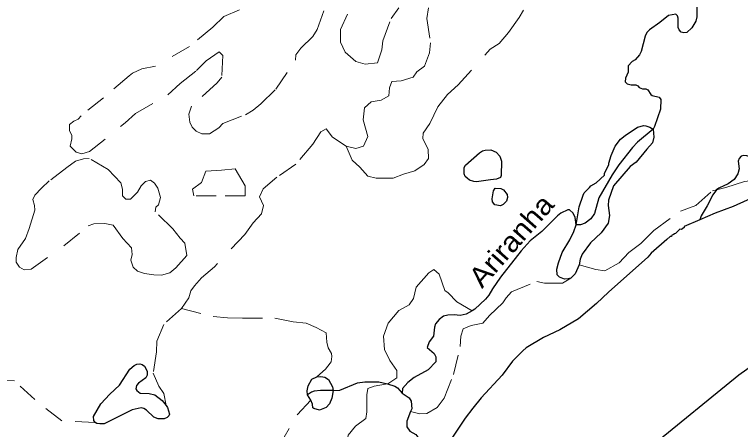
# Model space of a CAD drawing. Extents: x 344.9 to 371, y 7566.4 to 7594.3.
# Drawn here: x 363.484 to 367.111, y 7574.277 to 7576.351 of the extents above; entities that cross this region are included whole.
import ezdxf
from ezdxf.enums import TextEntityAlignment as Align

# ---------------------------------------------------------------- set-up
doc = ezdxf.new("R2010")
doc.units = 0
doc.header["$LTSCALE"] = 0.04
doc.linetypes.add('LONG_DASHED', pattern=[7.5, 6, -1.5])
doc.linetypes.add('SHORT_DASHED', pattern=[2.7, 1.5, -1.2])
for name, color, linetype, lineweight in [('17', 7, 'SHORT_DASHED', 13), ('2', 7, 'Continuous', 25), ('21', 7, 'SHORT_DASHED', 13), ('3', 7, 'LONG_DASHED', 25), ('55', 7, 'Continuous', 25), ('7', 7, 'Continuous', 25)]:
    doc.layers.add(name, color=color, linetype=linetype, lineweight=lineweight)
doc.layers.add('61', color=7, linetype='Continuous')

msp = doc.modelspace()

# ---------------------------------------------------------------- linework, layer by layer
at = {"layer": '17'}
for points in [[(365.1404, 7575.6937), (365.171, 7575.6239), (365.2095, 7575.5887), (365.2488, 7575.5427), (365.2915, 7575.5335), (365.3753, 7575.5327), (365.4272, 7575.5528), (365.4833, 7575.57), (365.5302, 7575.601), (365.5519, 7575.6311), (365.5503, 7575.6763), (365.5243, 7575.7324), (365.5251, 7575.7579), (365.5594, 7575.8065), (365.5996, 7575.8893), (365.6473, 7575.9521), (365.7, 7575.999), (365.8607, 7576.1777), (365.9059, 7576.207), (365.9519, 7576.261), (366.0055, 7576.3364), (366.0273, 7576.3724)], [(366.9919, 7575.4754), (367.0379, 7575.4866), (367.1305, 7575.5166), (367.1577, 7575.5202), (367.2629, 7575.5823), (367.3165, 7575.6332), (367.3382, 7575.6581), (367.4017, 7575.6781), (367.4607, 7575.6826), (367.5177, 7575.7012)], [(366.3051, 7575.0995), (366.3883, 7575.0766), (366.4328, 7575.0711), (366.5054, 7575.1101), (366.5534, 7575.1618), (366.6124, 7575.2072), (366.6786, 7575.2725), (366.812, 7575.3691), (366.8883, 7575.3972), (366.9708, 7575.4703), (366.9919, 7575.4754)], [(365.7709, 7574.8707), (365.6932, 7574.9162), (365.6513, 7574.9603), (365.6337, 7574.9713), (365.605, 7575.0529), (365.5785, 7575.0772), (365.5543, 7575.0595), (365.4903, 7574.9889), (365.4771, 7574.9316), (365.455, 7574.9007), (365.4043, 7574.8721), (365.3513, 7574.8081), (365.3271, 7574.7441), (365.3331, 7574.6777), (365.3593, 7574.6227), (365.3945, 7574.5727), (365.3935, 7574.5358), (365.3485, 7574.5063), (365.3482, 7574.5062)], [(365.4628, 7574.3666), (365.5089, 7574.3561), (365.5434, 7574.357), (365.596, 7574.3869), (365.6314, 7574.4332), (365.6768, 7574.5521), (365.7112, 7574.6927), (365.714, 7574.744), (365.7249, 7574.7812), (365.7657, 7574.7966), (365.8237, 7574.8084), (365.8573, 7574.8465), (365.9235, 7574.91), (365.9399, 7574.9354), (365.9671, 7574.9658), (366.0941, 7575.0166), (366.1313, 7575.0079), (366.2211, 7575.0079), (366.2632, 7575.0342)], [(364.3182, 7574.882), (364.4773, 7574.8419), (364.5479, 7574.8352), (364.6229, 7574.833), (364.7839, 7574.833), (364.8765, 7574.8154), (364.9405, 7574.8088), (364.9912, 7574.7867), (365.0419, 7574.7602), (365.0442, 7574.7139), (365.0508, 7574.6853), (365.0682, 7574.6578), (365.0687, 7574.6423), (365.0659, 7574.616), (365.0617, 7574.6091), (365.0377, 7574.5789), (364.994, 7574.5413)], [(365.3482, 7574.5062), (365.2817, 7574.4942), (365.2493, 7574.4831), (365.2438, 7574.4498), (365.2447, 7574.3657), (365.2401, 7574.3324), (365.1883, 7574.294), (365.1514, 7574.2497), (365.144, 7574.2053), (365.1643, 7574.1489), (365.168, 7574.112), (365.1634, 7574.0865), (365.1125, 7574.0431), (365.0737, 7574.0015), (365.0451, 7573.959), (365.0358, 7573.9146), (365.0478, 7573.893), (365.0599, 7573.8514), (365.1141, 7573.8251)], [(364.8063, 7574.1953), (364.8961, 7574.3501), (364.9638, 7574.4239)]]:
    msp.add_lwpolyline(points, dxfattribs=at)
at = {"layer": '2'}
msp.add_line((364.9701, 7574.5286), (364.994, 7574.5413), dxfattribs=at)
for points in [[(366.3574, 7575.4871), (366.3638, 7575.4943), (366.3892, 7575.5101), (366.4313, 7575.549), (366.4313, 7575.5562), (366.4535, 7575.6023), (366.4529, 7575.6086), (366.4647, 7575.6459), (366.4845, 7575.6928), (366.5123, 7575.7277), (366.5345, 7575.7468), (366.5965, 7575.7889), (366.6274, 7575.796), (366.6378, 7575.7952), (366.6584, 7575.7889), (366.6747, 7575.7781)], [(366.6747, 7575.7781), (366.6782, 7575.7389), (366.6711, 7575.7094), (366.6425, 7575.6785), (366.5905, 7575.6134), (366.5599, 7575.5911), (366.4773, 7575.4958), (366.4519, 7575.4228), (366.4503, 7575.3974), (366.4567, 7575.3466), (366.4503, 7575.3085), (366.4154, 7575.2608), (366.3623, 7575.2098), (366.3203, 7575.1537), (366.3092, 7575.1285), (366.3051, 7575.0995)], [(366.3256, 7575.4482), (366.3304, 7575.4593), (366.3574, 7575.4871)], [(367.2143, 7575.4554), (367.0745, 7575.3926), (366.984, 7575.3585), (366.9079, 7575.3257)], [(366.2899, 7575.3005), (366.3058, 7575.3895), (366.3256, 7575.4482)], [(366.9079, 7575.3257), (366.8299, 7575.2926), (366.8291, 7575.287), (366.8156, 7575.2775), (366.8077, 7575.2791), (366.7855, 7575.2568), (366.7783, 7575.256), (366.7775, 7575.2521), (366.768, 7575.2481), (366.7656, 7575.2425), (366.76, 7575.2417), (366.7425, 7575.2266), (366.6655, 7575.1584), (366.6473, 7575.1385)], [(366.2632, 7575.0342), (366.2498, 7575.0296), (366.2314, 7575.0282), (366.2074, 7575.0384), (366.1954, 7575.0504), (366.1938, 7575.0781), (366.201, 7575.1099), (366.22, 7575.1624), (366.2582, 7575.2259), (366.2788, 7575.2672), (366.2899, 7575.3005)], [(366.6473, 7575.1385), (366.451, 7574.9644), (366.3924, 7574.9074), (366.3011, 7574.8304), (366.2082, 7574.7756), (366.1264, 7574.7375), (366.0406, 7574.6851), (366.0231, 7574.6708), (365.9715, 7574.6184), (365.9199, 7574.5485), (365.8158, 7574.435), (365.7738, 7574.3842), (365.7349, 7574.3333), (365.6515, 7574.2087), (365.6308, 7574.1841)], [(366.3051, 7575.0995), (366.2853, 7575.0559), (366.2632, 7575.0342)], [(364.9479, 7574.45), (364.9463, 7574.4699), (364.9511, 7574.4961), (364.9701, 7574.5286)], [(364.994, 7574.5413), (365.0147, 7574.5429), (365.0353, 7574.5382), (365.0536, 7574.5279), (365.0735, 7574.49), (365.0763, 7574.4717)], [(365.0763, 7574.4717), (365.0702, 7574.4334), (365.0583, 7574.4056), (365.0408, 7574.3881), (365.0075, 7574.3746), (364.9789, 7574.3817), (364.9741, 7574.3857), (364.9725, 7574.4032), (364.9638, 7574.4239), (364.9479, 7574.45)]]:
    msp.add_lwpolyline(points, dxfattribs=at)
msp.add_lwpolyline([(365.8706, 7575.4308), (365.877, 7575.4705), (365.8857, 7575.4839), (365.9143, 7575.4824), (365.9263, 7575.4752), (365.9453, 7575.4522), (365.9477, 7575.4371), (365.9421, 7575.4181), (365.9254, 7575.4022), (365.912, 7575.3958), (365.8834, 7575.4005), (365.8722, 7575.4149)], close=True, dxfattribs=at)
at = {"layer": '21'}
msp.add_line((364.0729, 7576.0573), (364.0567, 7576.0455), dxfattribs=at)
for points in [[(364.0567, 7576.0455), (363.9286, 7575.9354), (363.8172, 7575.8457), (363.8018, 7575.8278), (363.7813, 7575.8176), (363.7595, 7575.8009), (363.7583, 7575.7715), (363.7711, 7575.7471), (363.7711, 7575.7292), (363.7621, 7575.6933), (363.7916, 7575.6626), (363.821, 7575.6549), (363.8582, 7575.6664), (364.0375, 7575.8099), (364.0887, 7575.856), (364.2501, 7575.9495), (364.3115, 7576.0058), (364.3935, 7576.0718), (364.4409, 7576.1191), (364.5062, 7576.164), (364.5241, 7576.146), (364.5203, 7576.0385), (364.4959, 7576.009), (364.3679, 7575.8925), (364.355, 7575.854), (364.3602, 7575.8131), (364.3717, 7575.7887), (364.3922, 7575.7682), (364.4204, 7575.7554), (364.4588, 7575.7554), (364.5049, 7575.7849), (364.5254, 7575.8066), (364.6381, 7575.8502), (364.6765, 7575.8726), (364.7149, 7575.9046), (364.7905, 7575.9776), (364.8878, 7576.1236), (364.8891, 7576.1505), (364.9147, 7576.1832), (364.9749, 7576.2408), (364.9954, 7576.2766), (365.0633, 7576.4598)], [(364.6074, 7576.374), (364.5293, 7576.342), (364.4755, 7576.2882), (364.359, 7576.1909), (364.1886, 7576.0929), (364.1195, 7576.0801), (364.0729, 7576.0573)], [(365.1474, 7576.3536), (365.1127, 7576.276), (365.1127, 7576.2135), (365.1358, 7576.1626), (365.1891, 7576.1162), (365.2354, 7576.1023), (365.2979, 7576.1093), (365.3188, 7576.1741), (365.3234, 7576.2204), (365.3651, 7576.3316), (365.4045, 7576.3849)], [(365.5527, 7576.3849), (365.5434, 7576.3316), (365.562, 7576.2089)], [(365.562, 7576.2089), (365.5573, 7576.1602), (365.5319, 7576.0931), (365.4948, 7576.0653), (365.4763, 7576.0375), (365.4161, 7576.019), (365.3697, 7576.0167), (365.3582, 7575.9842), (365.3535, 7575.9449), (365.3165, 7575.924), (365.2655, 7575.9148), (365.2331, 7575.8847), (365.2261, 7575.8245), (365.2493, 7575.7423), (365.2284, 7575.6937), (365.189, 7575.6821), (365.1404, 7575.6937)], [(365.1404, 7575.6937), (365.0732, 7575.7377), (365.0408, 7575.7793), (365.0153, 7575.7654), (364.9737, 7575.7029), (364.8903, 7575.6033), (364.7953, 7575.5385), (364.7258, 7575.4806), (364.7073, 7575.4401), (364.7281, 7575.3961), (364.7189, 7575.3544), (364.6772, 7575.3104), (364.6355, 7575.2525), (364.4826, 7575.0904), (364.4178, 7575.0349), (364.383, 7574.9955), (364.3645, 7574.97), (364.3553, 7574.9353), (364.3182, 7574.882)], [(364.3182, 7574.882), (364.2302, 7574.8021), (364.1955, 7574.7187), (364.1932, 7574.6655), (364.1769, 7574.5589), (364.2047, 7574.4941), (364.2302, 7574.457), (364.2426, 7574.3972)], [(363.8869, 7574.3127), (363.7198, 7574.3204), (363.5854, 7574.4265), (363.484, 7574.5208), (363.4109, 7574.5232), (363.3496, 7574.4784), (363.3095, 7574.4572), (363.2623, 7574.4383), (363.234, 7574.4195), (363.2033, 7574.3935), (363.1916, 7574.3746), (363.1939, 7574.3369), (363.2293, 7574.2756)]]:
    msp.add_lwpolyline(points, dxfattribs=at)
for points in [[(363.7451, 7575.5866), (363.6581, 7575.52), (363.6183, 7575.4841), (363.5863, 7575.4483), (363.5761, 7575.4265), (363.5838, 7575.397), (363.585, 7575.3727), (363.5569, 7575.2818), (363.5389, 7575.2318), (363.5005, 7575.1768), (363.4928, 7575.1371), (363.4928, 7575.1134), (363.5094, 7575.0891), (363.5325, 7575.075), (363.5671, 7575.0788), (363.731, 7575.1954), (363.8514, 7575.2946), (363.8809, 7575.3049), (363.9347, 7575.3061), (363.9769, 7575.2985), (364.0256, 7575.2319), (364.0679, 7575.1845), (364.0717, 7575.1512), (364.0653, 7575.123), (364.0768, 7575.0884), (364.0986, 7575.0692), (364.1332, 7575.057), (364.1806, 7575.0506), (364.2177, 7575.0493), (364.26, 7575.0609), (364.2907, 7575.0852), (364.3445, 7575.1467), (364.3355, 7575.2082), (364.3112, 7575.2338), (364.2753, 7575.2799), (364.187, 7575.3657), (364.1896, 7575.3881), (364.2036, 7575.3996), (364.2139, 7575.4368), (364.1998, 7575.4829), (364.1832, 7575.5085), (364.1639, 7575.5239), (364.1383, 7575.5175), (364.1166, 7575.4957), (364.0986, 7575.4637), (364.0641, 7575.4291), (364.0397, 7575.4291), (364.0231, 7575.4445), (364.0231, 7575.479), (364.0154, 7575.5098), (363.9526, 7575.5764), (363.8579, 7575.6321), (363.8284, 7575.6295), (363.7887, 7575.618)], [(364.3794, 7575.4448), (364.3738, 7575.4784), (364.4185, 7575.512), (364.4408, 7575.568), (364.519, 7575.5736), (364.586, 7575.5792), (364.6028, 7575.5512), (364.6363, 7575.4952), (364.6363, 7575.4448), (364.4911, 7575.4448)]]:
    msp.add_lwpolyline(points, close=True, dxfattribs=at)
at = {"layer": '3'}
msp.add_line((364.2224, 7574.4219), (364.2426, 7574.3972), dxfattribs=at)
msp.add_lwpolyline([(365.8627, 7575.5255), (365.7919, 7575.5153), (365.7785, 7575.5167), (365.7567, 7575.5241), (365.7456, 7575.5329), (365.7354, 7575.5422), (365.7303, 7575.5556), (365.7299, 7575.5866), (365.7377, 7575.5982), (365.8075, 7575.6604), (365.8214, 7575.6692), (365.8348, 7575.6733), (365.8639, 7575.6752), (365.8898, 7575.6636), (365.9092, 7575.6433), (365.9175, 7575.6178), (365.916, 7575.5464), (365.9119, 7575.5362), (365.8915, 7575.5279)], close=True, dxfattribs=at)
for points in [[(363.8869, 7574.3127), (363.8813, 7574.3224), (363.8785, 7574.3423), (363.915, 7574.4049), (363.9599, 7574.4536), (364.008, 7574.4994), (364.0607, 7574.5792), (364.0819, 7574.5977), (364.0949, 7574.6047), (364.1097, 7574.6061), (364.1226, 7574.6019), (364.1332, 7574.594), (364.1466, 7574.5685), (364.1466, 7574.549), (364.141, 7574.5356), (364.1035, 7574.5087), (364.0933, 7574.4971), (364.091, 7574.4809), (364.0961, 7574.4716), (364.1127, 7574.4596), (364.1571, 7574.4568), (364.1853, 7574.4498), (364.2224, 7574.4219)], [(364.2426, 7574.3972), (364.2493, 7574.3867), (364.2577, 7574.3543), (364.2549, 7574.3455), (364.2471, 7574.3377), (364.2313, 7574.3307), (364.2026, 7574.3312), (364.1795, 7574.3386), (364.1429, 7574.3743), (364.1304, 7574.3822), (364.1175, 7574.3854), (364.0712, 7574.3761), (363.9327, 7574.3057), (363.91, 7574.3053), (363.8948, 7574.308), (363.8869, 7574.3127)]]:
    msp.add_lwpolyline(points, dxfattribs=at)
at = {"layer": '55'}
for points in [[(366.6747, 7575.7781), (366.5968, 7575.7136), (366.5709, 7575.6864), (366.504, 7575.6004), (366.4699, 7575.5499), (366.4031, 7575.4354), (366.3813, 7575.3576), (366.3635, 7575.3303), (366.3349, 7575.3085), (366.3117, 7575.3003), (366.2899, 7575.3005)], [(367.4854, 7574.8196), (367.1023, 7574.5489), (366.6611, 7574.1888), (366.3867, 7573.8395), (366.1501, 7573.478), (365.7032, 7572.9063), (365.6623, 7572.8301), (365.4153, 7572.3691)], [(365.0763, 7574.4717), (365.0129, 7574.4722), (364.982, 7574.4683), (364.9677, 7574.4633), (364.9479, 7574.45)]]:
    msp.add_lwpolyline(points, dxfattribs=at)
at = {"layer": '7'}
for points in [[(366.8952, 7576.4399), (366.8929, 7576.3388), (366.8878, 7576.3187), (366.8675, 7576.285), (366.8435, 7576.2608), (366.8287, 7576.2594), (366.8144, 7576.2622), (366.8043, 7576.2746), (366.8001, 7576.287), (366.8001, 7576.3335), (366.7969, 7576.3445), (366.7876, 7576.3533), (366.7521, 7576.3459), (366.7083, 7576.3106), (366.6571, 7576.2753), (366.6432, 7576.261), (366.6354, 7576.243), (366.6155, 7576.1668), (366.6068, 7576.1502), (366.5855, 7576.1255), (366.5698, 7576.1158), (366.5505, 7576.0945), (366.5496, 7576.0638), (366.5366, 7576.0328), (366.5353, 7576.0153), (366.545, 7576.0042), (366.5643, 7575.9996), (366.5883, 7575.9996), (366.5989, 7575.9945), (366.6054, 7575.9864), (366.6215, 7575.9804), (366.6381, 7575.98), (366.6487, 7575.9749), (366.663, 7575.9509), (366.6704, 7575.9458), (366.705, 7575.9389), (366.7128, 7575.9269), (366.7119, 7575.878), (366.6819, 7575.7912), (366.6747, 7575.7781)], [(367.1975, 7575.623), (367.143, 7575.6451), (367.1255, 7575.6467), (367.1135, 7575.6426), (367.1038, 7575.6315), (367.1001, 7575.619), (367.104, 7575.5797), (367.0976, 7575.5548), (367.08, 7575.5273), (367.0496, 7575.5056), (367.0034, 7575.4841), (366.9919, 7575.4754)], [(366.9919, 7575.4754), (366.9721, 7575.4505), (366.9444, 7575.3944), (366.9149, 7575.3452), (366.9079, 7575.3257)], [(366.2899, 7575.3005), (366.2847, 7575.3366), (366.2746, 7575.3583), (366.2566, 7575.3754), (366.2487, 7575.3749), (366.2141, 7575.3585), (366.1966, 7575.3456), (366.1181, 7575.2667), (366.0595, 7575.2194), (366.0148, 7575.1702), (365.9115, 7575.0387), (365.8714, 7574.98), (365.8543, 7574.9486), (365.8368, 7574.9285), (365.7833, 7574.8788), (365.7709, 7574.8707)], [(365.7709, 7574.8707), (365.7408, 7574.853), (365.7103, 7574.8479), (365.6801, 7574.851), (365.6483, 7574.8495), (365.6277, 7574.8439), (365.6062, 7574.8272), (365.588, 7574.8058), (365.5816, 7574.7891), (365.5768, 7574.7439), (365.5554, 7574.7153), (365.5459, 7574.6875), (365.5814, 7574.6577), (365.5888, 7574.6397), (365.5883, 7574.6155), (365.5514, 7574.5755), (365.4803, 7574.5365), (365.4485, 7574.5116), (365.4222, 7574.4824), (365.42, 7574.4597)], [(365.0763, 7574.4717), (365.1086, 7574.4735), (365.1972, 7574.5107), (365.2341, 7574.5164), (365.3047, 7574.5162), (365.3482, 7574.5062)], [(365.3482, 7574.5062), (365.384, 7574.4934), (365.3983, 7574.4851), (365.42, 7574.4597)], [(365.42, 7574.4597), (365.456, 7574.4355), (365.4661, 7574.4196), (365.4688, 7574.381), (365.4628, 7574.3666)], [(365.4628, 7574.3666), (365.4434, 7574.319), (365.4442, 7574.2905), (365.4585, 7574.269), (365.4895, 7574.2523), (365.5038, 7574.2325)]]:
    msp.add_lwpolyline(points, dxfattribs=at)

# ---------------------------------------------------------------- texts
at = {"layer": '61', "width": 1.1}
msp.add_text('Ariranha', height=0.1, rotation=48.706, dxfattribs=at).set_placement((366.0032, 7575.1877), align=Align.CENTER)

doc.saveas('drawing.dxf')
